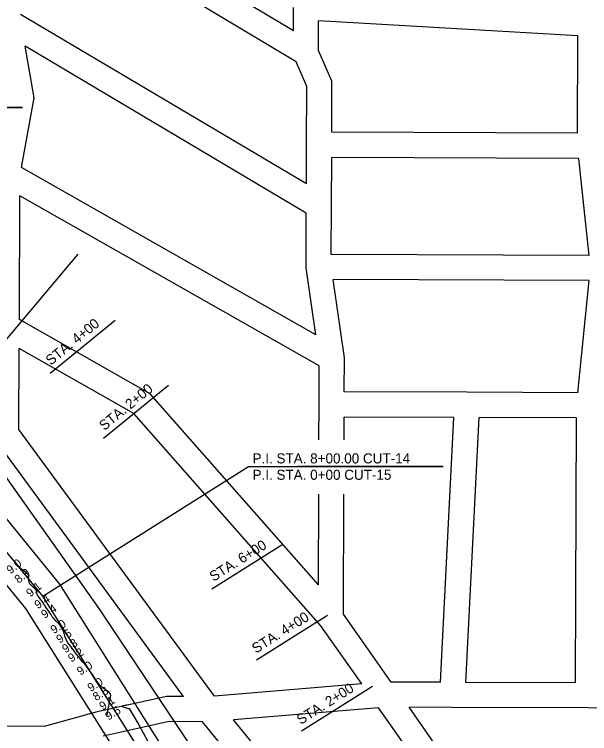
# Model space of a CAD drawing. Extents: x 497696 to 505896, y 1319278 to 1325078.
# Drawn here: x 502536 to 503906, y 1320945 to 1322658 of the extents above; entities that cross this region are included whole.
import ezdxf

# ---------------------------------------------------------------- set-up
doc = ezdxf.new("R2010")
doc.units = 0
for name, color, linetype in [('Level 1', 7, 'Continuous'), ('Level 32', 7, 'Continuous'), ('Level 49', 7, 'Continuous'), ('Level 5', 7, 'Continuous'), ('Level 50', 7, 'Continuous'), ('Level 56', 7, 'Continuous'), ('Level 6', 7, 'Continuous')]:
    doc.layers.add(name, color=color, linetype=linetype)

msp = doc.modelspace()

# ---------------------------------------------------------------- linework, layer by layer
at = {"layer": 'Level 1'}
for points in [[(502573.6, 1321300.5), (502572.6, 1321302.3), (502571.5, 1321305.4), (502570.3, 1321309.7), (502569.6, 1321313.2), (502569.5, 1321315.7), (502570, 1321317.3), (502570.4, 1321318.8), (502570.7, 1321320.3), (502571, 1321321.7), (502568.5, 1321324.6), (502563.2, 1321329.1), (502555.1, 1321335.1), (502547.9, 1321341.8), (502541.4, 1321349.1), (502535.7, 1321357.1)], [(502756.1, 1320987.1), (502759.7, 1321004), (502760.9, 1321010.6), (502761.7, 1321015.2), (502761.9, 1321018), (502762.5, 1321021.6), (502763.6, 1321026.1), (502765.2, 1321031.4), (502765.6, 1321035.9), (502765.1, 1321039.4), (502763.4, 1321042.1), (502759.9, 1321045.3), (502754.5, 1321049.2), (502747.3, 1321053.6), (502739.7, 1321060.9), (502731.7, 1321071.1), (502723.4, 1321084.1), (502715, 1321096), (502706.7, 1321106.8), (502698.3, 1321116.4), (502692.5, 1321123.2), (502689.4, 1321127), (502688.9, 1321127.9), (502687, 1321130.6), (502683.8, 1321135), (502679.3, 1321141.2), (502675.9, 1321145.7), (502673.8, 1321148.6), (502672.9, 1321149.8), (502670.8, 1321152.5), (502667.4, 1321156.8), (502662.8, 1321162.6), (502659.1, 1321169.5), (502656.2, 1321177.6), (502654.1, 1321186.8), (502650, 1321195.9), (502643.8, 1321204.8), (502635.5, 1321213.5), (502629.7, 1321219.9), (502626.2, 1321223.8), (502625.2, 1321225.4), (502624.3, 1321226.9), (502623.4, 1321228.4), (502622.5, 1321229.9), (502620.5, 1321233), (502617.2, 1321237.7), (502612.7, 1321244.2), (502609.5, 1321248.9), (502607.4, 1321251.9), (502606.5, 1321253.2), (502604.1, 1321256.6), (502600.2, 1321262.2), (502594.9, 1321269.8), (502591.2, 1321275.3), (502589.1, 1321278.6), (502588.8, 1321279.7), (502589, 1321280.9), (502589.5, 1321282.1), (502590.6, 1321283.4), (502589.4, 1321285.8), (502586.1, 1321289.5), (502580.7, 1321294.4), (502576.8, 1321297.8), (502574.4, 1321299.9), (502573.6, 1321300.5)], [(502807.3, 1321014.1), (502794.8, 1321011.8), (502792.6, 1321010.4), (502794.4, 1321008.9), (502800.2, 1321007.2), (502804.7, 1321006), (502807.8, 1321005.3), (502809.6, 1321005.1), (502817.7, 1320992.1), (502832.1, 1320966.6), (502852.9, 1320928.3)]]:
    msp.add_lwpolyline(points, dxfattribs=at)
at = {"layer": 'Level 32'}
for p, q in [((503206.9, 1322545.1), (502666.9, 1322870)), ((503200.8, 1322618.9), (502791.9, 1322864.8)), ((503200.8, 1322618.9), (503201, 1322675.1)), ((503231.6, 1322254.8), (502550.8, 1322658.4)), ((503260.6, 1322572.2), (503260.8, 1322643.2)), ((503878.6, 1322607.7), (503260.8, 1322643.2)), ((503877.7, 1322375.3), (503878.6, 1322607.7)), ((502582.7, 1322459.4), (502561.4, 1322582.4)), ((503231.4, 1322185.2), (502561.4, 1322582.4)), ((502552.6, 1322293.4), (502582.7, 1322459.4)), ((503877.7, 1322375.3), (503292.1, 1322377.6)), ((503231.6, 1322254.8), (503232, 1322347.8)), ((503291.4, 1322202.1), (503291.9, 1322317.6)), ((503880.6, 1322315.3), (503291.9, 1322317.6)), ((503905.3, 1322084.3), (503880.6, 1322315.3)), ((503253.9, 1321894.9), (502552.6, 1322293.4)), ((502547.9, 1321931.7), (502549.1, 1322226.4)), ((503262.2, 1321821.2), (502549.1, 1322226.4)), ((503291, 1322086.7), (503291.4, 1322202.1)), ((503230.8, 1322054.7), (503231.4, 1322185.2)), ((503905.3, 1322084.3), (503291, 1322086.7)), ((503253.9, 1321894.9), (503230.8, 1322054.7)), ((503322.3, 1321840.7), (503295.5, 1322026.7)), ((503905.5, 1322024.3), (503295.5, 1322026.7)), ((503878.1, 1321757.2), (503905.5, 1322024.3)), ((502546.9, 1321669.6), (502547.7, 1321862.8)), ((503322, 1321759.4), (503322.3, 1321840.7)), ((503261.9, 1321729.6), (503262.2, 1321821.2)), ((503614.8, 1321758.3), (503322, 1321759.4)), ((503878.1, 1321757.2), (503614.8, 1321758.3)), ((503261.5, 1321645.4), (503261.9, 1321729.6)), ((503321.5, 1321645.4), (503321.7, 1321699.4)), ((503583.1, 1321698.4), (503321.7, 1321699.4)), ((503551.2, 1321067.7), (503583.1, 1321698.4)), ((503611.3, 1321067.5), (503643.2, 1321698.2)), ((503875.1, 1321697.3), (503643.2, 1321698.2)), ((503872.6, 1321066.5), (503875.1, 1321697.3)), ((503012.8, 1321034.8), (502546.9, 1321669.6)), ((502939.1, 1321033.8), (502486.8, 1321650)), ((503260.2, 1321299.6), (503261, 1321515.9)), ((503319.9, 1321230), (503321, 1321515.9)), ((503433.9, 1321068.2), (503319.9, 1321230)), ((503363.6, 1321063.8), (503266.3, 1321201.9)), ((503363.6, 1321063.8), (503012.8, 1321034.8)), ((503551.2, 1321067.7), (503433.9, 1321068.2)), ((503872.6, 1321066.5), (503611.3, 1321067.5)), ((502898.5, 1321033.9), (502732.9, 1320997.3)), ((502939.1, 1321033.8), (502898.5, 1321033.9)), ((502732.9, 1320997.3), (502606.9, 1320962.3)), ((503403.7, 1321006.9), (503057.9, 1320978.3)), ((503648.9, 1320658.9), (503403.7, 1321006.9)), ((503579.6, 1321007.6), (503476.3, 1321008)), ((503690.7, 1320703.7), (503476.3, 1321008)), ((503902.4, 1321006.4), (503579.6, 1321007.6)), ((504036.3, 1321005.9), (503902.4, 1321006.4)), ((503425.8, 1320528.5), (503057.9, 1320978.3)), ((502606.9, 1320962.3), (502325.6, 1320963.4)), ((502904.9, 1320973.9), (502747.4, 1320939.1)), ((502984.3, 1320973.6), (502904.9, 1320973.9)), ((503393.9, 1320472.8), (502984.3, 1320973.6))]:
    msp.add_line(p, q, dxfattribs=at)
for points in [[(503292.1, 1322377.6), (503292.6, 1322499.3), (503260.6, 1322572.2)], [(503232, 1322347.8), (503232.5, 1322486.8), (503206.9, 1322545.1)], [(503260.2, 1321299.6), (502859.1, 1321754.9), (502547.9, 1321931.7)], [(503266.3, 1321201.9), (502820.8, 1321707.7), (502547.7, 1321862.8)]]:
    msp.add_lwpolyline(points, dxfattribs=at)
at = {"layer": 'Level 5'}
msp.add_lwpolyline([(504107.7, 1319477.9), (503822.6, 1319798.4), (503531.7, 1320041), (503232.9, 1320458.6), (503199.8, 1320550.4), (502737.7, 1321243.7), (502440.6, 1321661.5), (502255.8, 1321845.1), (502052.9, 1321934.2), (501254.5, 1322198), (501046.8, 1322407), (500972.3, 1322582.2), (500898.1, 1322849.2), (500933, 1323374.1), (501045.4, 1323950.4), (501078.5, 1324015.1), (501460.9, 1324322.7), (501588.1, 1324548.9), (501884.4, 1324877.9)], dxfattribs=at)
at = {"layer": 'Level 50'}
for p, q in [((502644.3, 1321301.7), (502339.7, 1321674.1)), ((502563, 1321243.1), (502394.9, 1321448.6)), ((503073.4, 1320621.5), (502644.3, 1321301.7)), ((502987.6, 1320570.1), (502563, 1321243.1))]:
    msp.add_line(p, q, dxfattribs=at)
at = {"layer": 'Level 56'}
for p, q in [((502091.7, 1322436.3), (502555.6, 1322436.3)), ((502555.6, 1322436.3), (502209.9, 1322436.3)), ((502307.1, 1321635.1), (502688, 1322087.6)), ((502621.4, 1321803.6), (502776.2, 1321930.2)), ((502748, 1321648.7), (502902.8, 1321775.3)), ((502603.6, 1321272.4), (503093.3, 1321581.4)), ((503093.3, 1321581.4), (503557.3, 1321581.4)), ((503557.3, 1321581.4), (503211.6, 1321581.4)), ((503006.3, 1321290), (503175.5, 1321396.7)), ((503113.1, 1321120.9), (503282.2, 1321227.6)), ((503219.8, 1320951.7), (503388.9, 1321058.4))]:
    msp.add_line(p, q, dxfattribs=at)
at = {"layer": 'Level 6'}
for p, q in [((502603.6, 1321272.4), (502307.1, 1321635.1)), ((503030.5, 1320595.8), (502603.6, 1321272.4))]:
    msp.add_line(p, q, dxfattribs=at)

# ---------------------------------------------------------------- texts
at = {"layer": 'Level 49'}
for s, rotation, p in [('9.0', 39.2692, (502526.7, 1321324.4)), ('8.9', 39.2692, (502546.3, 1321301.9)), ('9.1', 39.2692, (502573.9, 1321269.4)), ('9.4', 32.2506, (502591.5, 1321241.5)), ('9.4', 32.2506, (502607.5, 1321218.5)), ('9.0', 32.2506, (502629.8, 1321182.1)), ('9.5', 32.2506, (502643.5, 1321159.5)), ('9.3', 32.2506, (502657.5, 1321136.5)), ('9.2', 32.2506, (502671.5, 1321114.5)), ('9.0', 32.2506, (502692.8, 1321083.1)), ('9.0', 32.2506, (502717.8, 1321044.1)), ('8.8', 32.2506, (502730.5, 1321022.5)), ('9.1', 32.2506, (502746.1, 1320999.9)), ('9.6', 32.2506, (502760.1, 1320976.2))]:
    msp.add_text(s, height=20, rotation=rotation, dxfattribs=at).set_placement(p)
at = {"layer": 'Level 56'}
for s, rotation, p in [('STA. 4+00', 39.1814, (502622.5, 1321821.4)), ('STA. 2+00', 39.3307, (502750.2, 1321665.9)), ('STA. 6+00', 32.2222, (503010.3, 1321306.8)), ('STA. 4+00', 32.2222, (503111.3, 1321135.5)), ('STA. 2+00', 32.2222, (503218.1, 1320965.9))]:
    msp.add_text(s, height=24, rotation=rotation, dxfattribs=at).set_placement(p)
for s, p in [('P.I. STA. 8+00.00 CUT-14', (503103.3, 1321588.9)), ('P.I. STA. 0+00 CUT-15', (503103.3, 1321549.9))]:
    msp.add_text(s, height=24, dxfattribs=at).set_placement(p)

doc.saveas('drawing.dxf')
